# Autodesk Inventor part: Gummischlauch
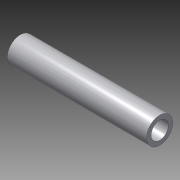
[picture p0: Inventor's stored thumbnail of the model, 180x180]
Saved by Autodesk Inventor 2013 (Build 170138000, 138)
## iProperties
Created: 2012-07
Part Number: Gummischlauch
Material: PVC, hart
Document SubType Name: Modeling
Designer: rYan
Mass: 7.31865 g
Surface Area: 53.9097 cm^2
Volume: 5.22761 cm^3
Density: 1.4 g/cm^3
Author: rYan
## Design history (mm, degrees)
sketch "Skizze1"
  geometry: C1 r 4 at (0, 0); C2 r 6 at (0, 0); 1 further point
  constraints: 2 centre point, 2 coincident
  dimensions: "d0" = 8 diameter of C1; "d1" = 2 radial gap between concentric circles of C2 C1
extrude "Extrusion1" new body sketch "Skizze1" distance "d2" = 64; taper "d3" = 0 deg
node "Volumenkörper1"
